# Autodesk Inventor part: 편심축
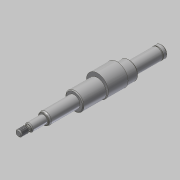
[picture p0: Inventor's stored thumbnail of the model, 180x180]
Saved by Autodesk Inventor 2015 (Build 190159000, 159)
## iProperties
Created: 2015-09
Part Number: 편심축
Material: 강철, 연강
Document SubType Name: Modeling
Designer: mduedu
Density: 1 g/cm^3
Appearance: 강철
Author: mduedu
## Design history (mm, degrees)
sketch "스케치1"
  geometry: L1 (-91, 0)-(91, 0); L2 (-91, 0)-(-91, 7.5); L3 (-91, 7.5)-(-49.85, 7.5); L4 (-49.85, 7.5)-(-49.85, 11.5); L5 (-49.85, 11.5)-(20.15, 11.5); L6 (20.15, 11.5)-(20.15, 7.5); L7 (20.15, 7.5)-(59.15, 7.5); L8 (59.15, 7.5)-(59.15, 5); L9 (59.15, 5)-(78.15, 5); L10 (78.15, 5)-(78.15, 3); L11 (78.15, 3)-(80.15, 3); L12 (81.882, 4)-(91, 4); L13 (91, 4)-(91, 0); L14 (80.15, 3)-(81.882, 4); 2 further points
  constraints: 28 end point, 9 parallel, 2 perpendicular, 1 coincident, 1 collinear, 1 horizontal, 1 midpoint
  dimensions: "d0" = 41.15 distance of L2.end L3.end; "d2" = 70 distance of L4.end L5.end; "d3" = 39 distance of L6.end L7.end; "d4" = 182 distance of L1.start L1.end; "d5" = 19 distance of L8.end L9.end; "d7" = 8 diameter of L12 L1; "d8" = 6 diameter of L11 L1; "d9" = 10 diameter of L9 L1; "d10" = 15 diameter of L7 L1; "d11" = 23 diameter of L5 L1; "d12" = 15 diameter of L3 L1; "d40" = 30 deg angle of L14 L12; "d41" = 2 distance of L10.end L11.end; "d42" = 3.73205 horizontal distance of L12.start L10.end (derived)
revolve "회전1" sketch "스케치1" stored, may be unused: angle "d13" = 90 deg
fillet "모깎기1" dims "d43" = 0.6
sketch "스케치2"
  geometry: L1 (-91, 7.5)-(-49.85, 7.5) reference; L2 (-91, -7.5)-(-91, 7.5) reference; L3 (91, -4)-(91, 4) reference; L4 (-91, 0)-(91, 0); L5 (-86, 7.5)-(-84.85, 7.5); L6 (-84.85, 7.5)-(-84.85, 7.15); L7 (-84.85, 7.15)-(-86, 7.15); L8 (-86, 7.15)-(-86, 7.5); 1 further point
  constraints: 10 end point, 2 midpoint, 2 parallel, 1 horizontal, 1 perpendicular, 1 point on line
  dimensions: "d14" = 5 distance between parallel lines of L8 L2; "d15" = 14.3 diameter of L7 L4; "d16" = 1.15 distance of L6.end L7.end
revolve "회전2" sketch "스케치2" stored, may be unused: angle "d17" = 90 deg
node "작업 평면1"
sketch "스케치3"
  geometry: C1 r 11.5 at (0, 0) reference; C2 r 14 at (0, 2.5); 1 further point
  constraints: 1 centre point, 1 tangent, 1 vertical alignment
  dimensions: "d19" = 28 diameter of C2
extrude "돌출1" join sketch "스케치3" distance "d21" = 25; taper "d22" = 0 deg
node "작업 평면2"
sketch "스케치4"
  geometry: L1 (9.5, 7.5)-(9.5, -7.5) reference; L2 (-9.5, 5)-(-9.5, -5) reference; L3 (9.5, 0)-(-9.5, 0); L4 (-5, -1.5)-(4, -1.5); L5 (4, 1.5)-(-5, 1.5); A1 r 1.5 centre (4, 0) between (4, -1.5) and (4, 1.5); A2 r 1.5 centre (-5, 0) between (-5, 1.5) and (-5, -1.5); 1 further point
  constraints: 6 end point, 4 point on circle, 4 tangent, 2 centre point, 2 midpoint, 2 parallel, 1 point on line
  dimensions: "d23" = 3 distance between parallel lines of L5 L4; "d25" = 12 dimension on A2 A1; "d26" = 3 distance edge to line of A2 L2
extrude "돌출2" cut sketch "스케치4" distance "d27" = 1.8; taper "d28" = 0 deg
chamfer "모따기1" distance "d29" = 1; stored, may be unused: second distance "d30" = 2, angle "d31" = 45 deg
sketch "스케치5"
  geometry: L1 (80.289, 3.08)-(81.882, 4) reference; L2 (81.882, 4)-(91, 4) reference; L3 (91, 4)-(91, -4) reference; L4 (91, -4)-(81.882, -4) reference; L5 (81.882, -4)-(80.289, -3.08) reference; L6 (79.989, -3)-(78.75, -3) reference; L7 (78.15, -3.6)-(78.15, -5) reference; L8 (78.15, -5)-(75.15, -5) reference; L9 (75.15, -5)-(75.15, -3.2) reference; L10 (75.15, -3.2)-(63.15, -3.2) reference; L11 (63.15, -3.2)-(63.15, -5) reference; L12 (63.15, -5)-(59.15, -5) reference; L13 (59.15, -5)-(59.15, -7.5) reference; L14 (59.15, -7.5)-(20.15, -7.5) reference; L15 (20.15, -7.5)-(20.15, -10.5) reference; L16 (20.15, -10.5)-(19.15, -11.5) reference; L17 (19.15, -11.5)-(-9.35, -11.5) reference; L18 (-9.35, -11.5)-(-34.35, -11.5) reference; L19 (-34.35, -11.5)-(-48.85, -11.5) reference; L20 (-48.85, -11.5)-(-49.85, -10.5) reference; L21 (-49.85, -10.5)-(-49.85, -7.5) reference; L22 (-49.85, -7.5)-(-84.85, -7.5) reference; L23 (-84.85, -7.5)-(-84.85, -7.15) reference; L24 (-84.85, -7.15)-(-86, -7.15) reference; L25 (-86, -7.15)-(-86, -7.5) reference; L26 (-86, -7.5)-(-90, -7.5) reference; L27 (-90, -7.5)-(-91, -6.5) reference; L28 (-91, -6.5)-(-91, 6.5) reference; L29 (-91, 6.5)-(-90, 7.5) reference; L30 (-90, 7.5)-(-86, 7.5) reference; L31 (-86, 7.5)-(-86, 7.15) reference; L32 (-86, 7.15)-(-84.85, 7.15) reference; L33 (-84.85, 7.15)-(-84.85, 7.5) reference; L34 (-84.85, 7.5)-(-49.85, 7.5) reference; L35 (-49.85, 7.5)-(-49.85, 10.5) reference; L36 (-49.85, 10.5)-(-48.85, 11.5) reference; L37 (-48.85, 11.5)-(-34.35, 11.5) reference; L38 (-34.35, 11.5)-(-34.35, 16.5) reference; L39 (-34.35, 16.5)-(-9.35, 16.5) reference; L40 (-9.35, 16.5)-(-9.35, 11.5) reference; L41 (-9.35, 11.5)-(19.15, 11.5) reference; L42 (19.15, 11.5)-(20.15, 10.5) reference; L43 (20.15, 10.5)-(20.15, 7.5) reference; L44 (20.15, 7.5)-(59.15, 7.5) reference; L45 (59.15, 7.5)-(59.15, 5) reference; L46 (59.15, 5)-(78.15, 5) reference; L47 (78.15, 5)-(78.15, 3.6) reference; L48 (78.75, 3)-(79.989, 3) reference; L49 (0, 0)-(91, 0); L50 (59.15, -6.55)-(57.505, -7.5); L51 (57.505, -7.5)-(59.15, -7.5); L52 (59.15, -7.5)-(59.15, -6.55); A1 r 0.6 centre (79.989, 3.6) between (79.989, 3) and (80.289, 3.08) reference; A2 r 0.6 centre (79.989, -3.6) between (80.289, -3.08) and (79.989, -3) reference; A3 r 0.6 centre (78.75, -3.6) between (78.75, -3) and (78.15, -3.6) reference; A4 r 0.6 centre (78.75, 3.6) between (78.15, 3.6) and (78.75, 3) reference
  constraints: 8 end point, 2 point on line, 1 midpoint, 1 parallel, 1 perpendicular
  dimensions: "d44" = 30 deg angle of L50 L51; "d45" = 13.1 diameter of L50.start L49
revolve "회전3" sketch "스케치5" stored, may be unused: angle "d46" = 90 deg
fillet "모깎기2" dims "d47" = 4, "d48" = 0.5
feature "스레드1" dims "d32" = 10, "d33" = 0
chamfer "모따기2" distance "d34" = 1; stored, may be unused: second distance "d35" = 2, angle "d36" = 45 deg
chamfer "모따기3" distance "d37" = 1; stored, may be unused: second distance "d38" = 2, angle "d39" = 45 deg
node "솔리드1"
node "절단 모서리 투영1"
other parameters: "d18" = -29.5
